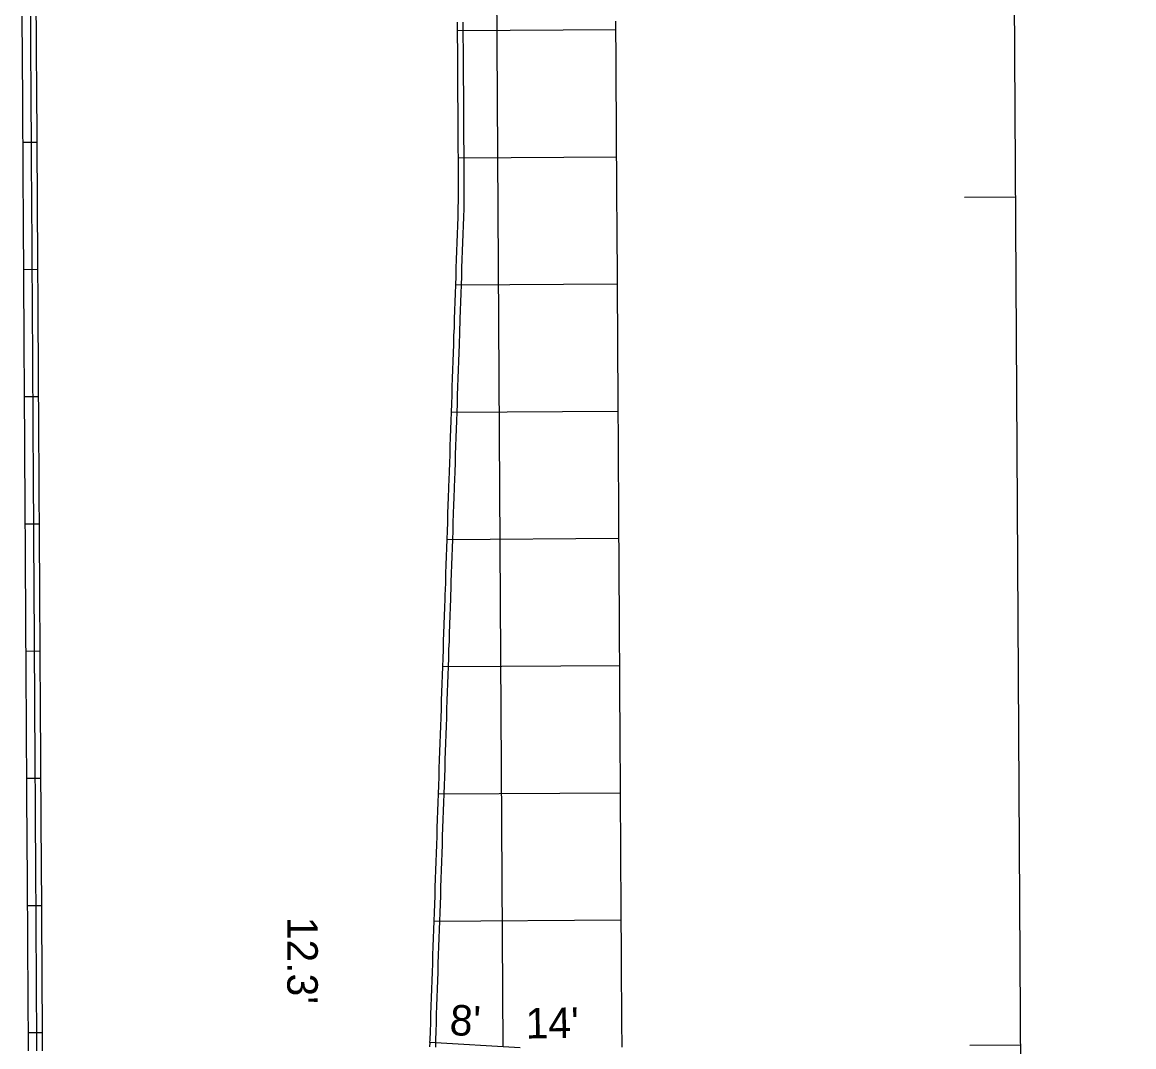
# Model space of a CAD drawing. Extents: x 2145147 to 2158018, y 137519 to 148068.
# Drawn here: x 2150693.6 to 2150824.7, y 145218.9 to 145339.8 of the extents above; entities that cross this region are included whole.
import ezdxf

# ---------------------------------------------------------------- set-up
doc = ezdxf.new("R2010")
doc.units = 0
for name, color, linetype in [('EX_Align', 7, 'Continuous'), ('PR_Dimensions', 7, 'Continuous'), ('PR_Joint_Contraction', 7, 'Continuous'), ('PR_Joint_Isolation', 7, 'Continuous'), ('PR_Joint_Long', 7, 'Continuous'), ('PR_Road_Concrete', 7, 'Continuous')]:
    doc.layers.add(name, color=color, linetype=linetype)

msp = doc.modelspace()

# ---------------------------------------------------------------- linework, layer by layer
at = {"layer": 'EX_Align'}
msp.add_line((2150824.67, 142998.65), (2150804.61, 146336.84), dxfattribs=at)
for points in [[(2150804.72, 145319.13), (2150810.72, 145319.17)], [(2150805.32, 145219.13), (2150811.32, 145219.17)]]:
    msp.add_lwpolyline(points, dxfattribs=at)
at = {"layer": 'PR_Joint_Contraction'}
for p, q in [((2150744.94, 145338.78), (2150763.6, 145338.89)), ((2150693.69, 145325.61), (2150695.35, 145325.62)), ((2150745.03, 145323.78), (2150763.69, 145323.89)), ((2150693.78, 145310.61), (2150695.44, 145310.62)), ((2150744.72, 145308.78), (2150763.78, 145308.9)), ((2150693.87, 145295.61), (2150695.53, 145295.62)), ((2150744.21, 145293.78), (2150763.87, 145293.9)), ((2150693.96, 145280.61), (2150695.62, 145280.62)), ((2150743.7, 145278.77), (2150763.96, 145278.9)), ((2150694.05, 145265.61), (2150695.72, 145265.62)), ((2150743.19, 145263.77), (2150764.05, 145263.9)), ((2150694.14, 145250.61), (2150695.81, 145250.62)), ((2150742.68, 145248.77), (2150764.14, 145248.9)), ((2150694.23, 145235.61), (2150695.9, 145235.62)), ((2150742.17, 145233.76), (2150764.23, 145233.9)), ((2150694.32, 145220.61), (2150695.99, 145220.62))]:
    msp.add_line(p, q, dxfattribs=at)
at = {"layer": 'PR_Joint_Isolation'}
msp.add_line((2150752.32, 145218.82), (2150741.68, 145219.46), dxfattribs=at)
at = {"layer": 'PR_Joint_Long'}
for points in [[(2150750.32, 145218.94), (2150743.61, 146336.79)], [(2150764.32, 145218.9), (2150764.32, 145219.89), (2150764.31, 145220.89), (2150764.31, 145221.89), (2150764.3, 145222.89), (2150764.29, 145223.89), (2150764.29, 145224.89), (2150764.28, 145225.89), (2150764.28, 145226.89), (2150764.27, 145227.89), (2150764.26, 145228.89), (2150764.26, 145229.89), (2150764.25, 145230.89), (2150764.25, 145231.89), (2150764.24, 145232.89), (2150764.23, 145233.89), (2150764.23, 145234.89), (2150764.22, 145235.89), (2150764.22, 145236.89), (2150764.21, 145237.89), (2150764.2, 145238.89), (2150764.2, 145239.89), (2150764.19, 145240.89), (2150764.19, 145241.89), (2150764.18, 145242.89), (2150764.17, 145243.89), (2150764.17, 145244.89), (2150764.16, 145245.89), (2150764.16, 145246.89), (2150764.15, 145247.89), (2150764.14, 145248.89), (2150764.14, 145249.89), (2150764.13, 145250.89), (2150764.13, 145251.89), (2150764.12, 145252.89), (2150764.11, 145253.89), (2150764.11, 145254.89), (2150764.1, 145255.89), (2150764.1, 145256.89), (2150764.09, 145257.89), (2150764.08, 145258.89), (2150764.08, 145259.89), (2150764.07, 145260.89), (2150764.07, 145261.89), (2150764.06, 145262.89), (2150764.05, 145263.89), (2150764.05, 145264.89), (2150764.04, 145265.89), (2150764.04, 145266.89), (2150764.03, 145267.89), (2150764.02, 145268.78), (2150764.02, 145268.89), (2150764.02, 145269.89), (2150764.01, 145270.89), (2150764.01, 145271.89), (2150764, 145272.49), (2150764, 145272.89), (2150763.99, 145273.89), (2150763.99, 145274.89), (2150763.98, 145275.89), (2150763.98, 145276.89), (2150763.97, 145277.89), (2150763.96, 145278.89), (2150763.96, 145279.89), (2150763.95, 145280.89), (2150763.95, 145281.89), (2150763.94, 145282), (2150763.94, 145282.89), (2150763.93, 145283.89), (2150763.93, 145284.89), (2150763.93, 145285.18), (2150763.92, 145285.89), (2150763.92, 145286.89), (2150763.91, 145287.89), (2150763.9, 145288.89), (2150763.9, 145289.89), (2150763.89, 145290.89), (2150763.89, 145291.89), (2150763.88, 145292.89), (2150763.87, 145293.89), (2150763.87, 145294.89), (2150763.86, 145295.89), (2150763.86, 145296.89), (2150763.85, 145297.89), (2150763.84, 145298.89), (2150763.84, 145299.89), (2150763.83, 145300.89), (2150763.83, 145301.89), (2150763.82, 145302.27), (2150763.82, 145302.89), (2150763.81, 145303.89), (2150763.81, 145304.18), (2150763.81, 145304.89), (2150763.8, 145305.89), (2150763.8, 145306.89), (2150763.79, 145307.89), (2150763.78, 145308.89), (2150763.78, 145309.89), (2150763.77, 145310.89), (2150763.77, 145311.89), (2150763.76, 145312.89), (2150763.75, 145313.89), (2150763.75, 145314.89), (2150763.74, 145315.89), (2150763.74, 145316.89), (2150763.73, 145317.89), (2150763.72, 145318.89), (2150763.72, 145319.89), (2150763.71, 145320.89), (2150763.71, 145321.89), (2150763.7, 145322.89), (2150763.69, 145323.89), (2150763.69, 145324.89), (2150763.68, 145325.89), (2150763.68, 145326.89), (2150763.67, 145327.89), (2150763.66, 145328.89), (2150763.66, 145329.89), (2150763.65, 145330.89), (2150763.65, 145331.89), (2150763.64, 145332.89), (2150763.63, 145333.89), (2150763.63, 145334.89), (2150763.62, 145335.89), (2150763.62, 145336.89), (2150763.61, 145337.89), (2150763.6, 145338.89), (2150763.6, 145339.89)]]:
    msp.add_lwpolyline(points, dxfattribs=at)
at = {"layer": 'PR_Road_Concrete'}
for points in [[(2150694.33, 145218.47), (2150694.33, 145219.47), (2150694.32, 145220.47), (2150694.32, 145221.47), (2150694.31, 145222.47), (2150694.3, 145223.47), (2150694.3, 145224.47), (2150694.29, 145225.47), (2150694.29, 145226.47), (2150694.28, 145227.47), (2150694.27, 145228.47), (2150694.27, 145229.47), (2150694.26, 145230.47), (2150694.26, 145231.47), (2150694.25, 145232.47), (2150694.24, 145233.47), (2150694.24, 145234.47), (2150694.23, 145235.47), (2150694.23, 145236.47), (2150694.22, 145237.47), (2150694.21, 145238.47), (2150694.21, 145239.47), (2150694.2, 145240.47), (2150694.19, 145241.47), (2150694.19, 145242.47), (2150694.18, 145243.47), (2150694.18, 145244.47), (2150694.17, 145245.47), (2150694.16, 145246.47), (2150694.16, 145247.47), (2150694.15, 145248.47), (2150694.15, 145249.47), (2150694.14, 145250.47), (2150694.13, 145251.47), (2150694.13, 145252.47), (2150694.12, 145253.47), (2150694.12, 145254.47), (2150694.11, 145255.47), (2150694.1, 145256.47), (2150694.1, 145257.47), (2150694.09, 145258.47), (2150694.09, 145259.47), (2150694.08, 145260.47), (2150694.07, 145261.47), (2150694.07, 145262.47), (2150694.06, 145263.47), (2150694.06, 145264.47), (2150694.05, 145265.47), (2150694.04, 145266.47), (2150694.04, 145267.47), (2150694.03, 145268.47), (2150694.03, 145269.47), (2150694.02, 145270.47), (2150694.01, 145271.47), (2150694.01, 145272.47), (2150694, 145273.47), (2150694, 145274.47), (2150693.99, 145275.47), (2150693.98, 145276.47), (2150693.98, 145277.47), (2150693.97, 145278.47), (2150693.97, 145279.47), (2150693.96, 145280.47), (2150693.95, 145281.47), (2150693.95, 145282.47), (2150693.94, 145283.47), (2150693.93, 145284.47), (2150693.93, 145285.47), (2150693.92, 145286.47), (2150693.92, 145287.47), (2150693.91, 145288.47), (2150693.9, 145289.47), (2150693.9, 145290.47), (2150693.89, 145291.47), (2150693.89, 145292.47), (2150693.88, 145293.47), (2150693.87, 145294.47), (2150693.87, 145295.47), (2150693.86, 145296.47), (2150693.86, 145297.47), (2150693.85, 145298.47), (2150693.84, 145299.47), (2150693.84, 145300.47), (2150693.83, 145301.47), (2150693.83, 145302.47), (2150693.82, 145303.47), (2150693.81, 145304.47), (2150693.81, 145305.47), (2150693.8, 145306.47), (2150693.8, 145307.47), (2150693.79, 145308.47), (2150693.78, 145309.47), (2150693.78, 145310.47), (2150693.77, 145311.47), (2150693.77, 145312.47), (2150693.76, 145313.47), (2150693.75, 145314.47), (2150693.75, 145315.47), (2150693.74, 145316.47), (2150693.74, 145317.47), (2150693.73, 145318.47), (2150693.72, 145319.47), (2150693.72, 145320.47), (2150693.71, 145321.47), (2150693.71, 145322.47), (2150693.7, 145323.47), (2150693.69, 145324.47), (2150693.69, 145325.47), (2150693.68, 145326.47), (2150693.68, 145327.47), (2150693.67, 145328.47), (2150693.66, 145329.47), (2150693.66, 145330.47), (2150693.65, 145331.47), (2150693.65, 145332.47), (2150693.64, 145333.47), (2150693.63, 145334.47), (2150693.63, 145335.47), (2150693.62, 145336.47), (2150693.62, 145337.47), (2150693.61, 145338.47), (2150693.6, 145339.47), (2150693.6, 145340.47)], [(2150695.33, 145218.48), (2150695.33, 145219.48), (2150695.32, 145220.48), (2150695.32, 145221.48), (2150695.31, 145222.48), (2150695.3, 145223.48), (2150695.3, 145224.48), (2150695.29, 145225.48), (2150695.29, 145226.48), (2150695.28, 145227.48), (2150695.27, 145228.48), (2150695.27, 145229.48), (2150695.26, 145230.48), (2150695.26, 145231.48), (2150695.25, 145232.48), (2150695.24, 145233.48), (2150695.24, 145234.48), (2150695.23, 145235.48), (2150695.23, 145236.48), (2150695.22, 145237.48), (2150695.21, 145238.48), (2150695.21, 145239.48), (2150695.2, 145240.48), (2150695.19, 145241.48), (2150695.19, 145242.48), (2150695.18, 145243.48), (2150695.18, 145244.48), (2150695.17, 145245.48), (2150695.16, 145246.48), (2150695.16, 145247.48), (2150695.15, 145248.48), (2150695.15, 145249.48), (2150695.14, 145250.48), (2150695.13, 145251.48), (2150695.13, 145252.48), (2150695.12, 145253.48), (2150695.12, 145254.48), (2150695.11, 145255.48), (2150695.1, 145256.48), (2150695.1, 145257.48), (2150695.09, 145258.48), (2150695.09, 145259.48), (2150695.08, 145260.48), (2150695.07, 145261.48), (2150695.07, 145262.48), (2150695.06, 145263.48), (2150695.06, 145264.48), (2150695.05, 145265.48), (2150695.04, 145266.48), (2150695.04, 145267.48), (2150695.03, 145268.48), (2150695.03, 145269.48), (2150695.02, 145270.48), (2150695.01, 145271.48), (2150695.01, 145272.48), (2150695, 145273.48), (2150695, 145274.48), (2150694.99, 145275.48), (2150694.98, 145276.48), (2150694.98, 145277.48), (2150694.97, 145278.48), (2150694.97, 145279.48), (2150694.96, 145280.48), (2150694.95, 145281.48), (2150694.95, 145282.48), (2150694.94, 145283.48), (2150694.93, 145284.48), (2150694.93, 145285.48), (2150694.92, 145286.48), (2150694.92, 145287.48), (2150694.91, 145288.48), (2150694.9, 145289.48), (2150694.9, 145290.48), (2150694.89, 145291.48), (2150694.89, 145292.48), (2150694.88, 145293.48), (2150694.87, 145294.48), (2150694.87, 145295.48), (2150694.86, 145296.48), (2150694.86, 145297.48), (2150694.85, 145298.48), (2150694.84, 145299.48), (2150694.84, 145300.48), (2150694.83, 145301.48), (2150694.83, 145302.48), (2150694.82, 145303.48), (2150694.81, 145304.48), (2150694.81, 145305.48), (2150694.8, 145306.48), (2150694.8, 145307.48), (2150694.79, 145308.48), (2150694.78, 145309.48), (2150694.78, 145310.48), (2150694.77, 145311.48), (2150694.77, 145312.48), (2150694.76, 145313.48), (2150694.75, 145314.48), (2150694.75, 145315.48), (2150694.74, 145316.48), (2150694.74, 145317.48), (2150694.73, 145318.48), (2150694.72, 145319.48), (2150694.72, 145320.48), (2150694.71, 145321.48), (2150694.71, 145322.48), (2150694.7, 145323.48), (2150694.69, 145324.48), (2150694.69, 145325.48), (2150694.68, 145326.48), (2150694.68, 145327.48), (2150694.67, 145328.48), (2150694.66, 145329.48), (2150694.66, 145330.48), (2150694.65, 145331.48), (2150694.65, 145332.48), (2150694.64, 145333.48), (2150694.63, 145334.48), (2150694.63, 145335.48), (2150694.62, 145336.48), (2150694.62, 145337.48), (2150694.61, 145338.48), (2150694.6, 145339.48), (2150694.6, 145340.48)], [(2150696, 145218.48), (2150695.99, 145219.48), (2150695.99, 145220.48), (2150695.98, 145221.48), (2150695.98, 145222.48), (2150695.97, 145223.48), (2150695.96, 145224.48), (2150695.96, 145225.48), (2150695.95, 145226.48), (2150695.95, 145227.48), (2150695.94, 145228.48), (2150695.93, 145229.48), (2150695.93, 145230.48), (2150695.92, 145231.48), (2150695.92, 145232.48), (2150695.91, 145233.48), (2150695.9, 145234.48), (2150695.9, 145235.48), (2150695.89, 145236.48), (2150695.89, 145237.48), (2150695.88, 145238.48), (2150695.87, 145239.48), (2150695.87, 145240.48), (2150695.86, 145241.48), (2150695.86, 145242.48), (2150695.85, 145243.48), (2150695.84, 145244.48), (2150695.84, 145245.48), (2150695.83, 145246.48), (2150695.83, 145247.48), (2150695.82, 145248.48), (2150695.81, 145249.48), (2150695.81, 145250.48), (2150695.8, 145251.48), (2150695.8, 145252.48), (2150695.79, 145253.48), (2150695.78, 145254.48), (2150695.78, 145255.48), (2150695.77, 145256.48), (2150695.76, 145257.48), (2150695.76, 145258.48), (2150695.75, 145259.48), (2150695.75, 145260.48), (2150695.74, 145261.48), (2150695.73, 145262.48), (2150695.73, 145263.48), (2150695.72, 145264.48), (2150695.72, 145265.48), (2150695.71, 145266.48), (2150695.7, 145267.48), (2150695.7, 145268.48), (2150695.69, 145269.48), (2150695.69, 145270.48), (2150695.68, 145271.48), (2150695.67, 145272.48), (2150695.67, 145273.48), (2150695.66, 145274.48), (2150695.66, 145275.48), (2150695.65, 145276.48), (2150695.64, 145277.48), (2150695.64, 145278.48), (2150695.63, 145279.48), (2150695.63, 145280.48), (2150695.62, 145281.48), (2150695.61, 145282.48), (2150695.61, 145283.48), (2150695.6, 145284.48), (2150695.6, 145285.48), (2150695.59, 145286.48), (2150695.58, 145287.48), (2150695.58, 145288.48), (2150695.57, 145289.48), (2150695.57, 145290.48), (2150695.56, 145291.48), (2150695.55, 145292.48), (2150695.55, 145293.48), (2150695.54, 145294.48), (2150695.53, 145295.48), (2150695.53, 145296.48), (2150695.52, 145297.48), (2150695.52, 145298.48), (2150695.51, 145299.48), (2150695.5, 145300.48), (2150695.5, 145301.48), (2150695.49, 145302.48), (2150695.49, 145303.48), (2150695.48, 145304.48), (2150695.47, 145305.48), (2150695.47, 145306.48), (2150695.46, 145307.48), (2150695.46, 145308.48), (2150695.45, 145309.48), (2150695.44, 145310.48), (2150695.44, 145311.48), (2150695.43, 145312.48), (2150695.43, 145313.48), (2150695.42, 145314.48), (2150695.41, 145315.48), (2150695.41, 145316.48), (2150695.4, 145317.48), (2150695.4, 145318.48), (2150695.39, 145319.48), (2150695.38, 145320.48), (2150695.38, 145321.48), (2150695.37, 145322.48), (2150695.37, 145323.48), (2150695.36, 145324.48), (2150695.35, 145325.48), (2150695.35, 145326.48), (2150695.34, 145327.48), (2150695.34, 145328.48), (2150695.33, 145329.48), (2150695.32, 145330.48), (2150695.32, 145331.48), (2150695.31, 145332.48), (2150695.31, 145333.48), (2150695.3, 145334.48), (2150695.29, 145335.48), (2150695.29, 145336.48), (2150695.28, 145337.48), (2150695.28, 145338.48), (2150695.27, 145339.48), (2150695.26, 145340.48)], [(2150741.68, 145219.46), (2150741.69, 145219.75), (2150741.73, 145220.75), (2150741.76, 145221.75), (2150741.79, 145222.75), (2150741.83, 145223.75), (2150741.86, 145224.75), (2150741.9, 145225.75), (2150741.93, 145226.75), (2150741.96, 145227.75), (2150742, 145228.75), (2150742.03, 145229.75), (2150742.07, 145230.76), (2150742.1, 145231.76), (2150742.13, 145232.76), (2150742.17, 145233.76), (2150742.2, 145234.76), (2150742.24, 145235.76), (2150742.27, 145236.76), (2150742.3, 145237.76), (2150742.34, 145238.76), (2150742.37, 145239.76), (2150742.41, 145240.76), (2150742.44, 145241.76), (2150742.47, 145242.76), (2150742.51, 145243.76), (2150742.54, 145244.76), (2150742.58, 145245.76), (2150742.61, 145246.76), (2150742.64, 145247.76), (2150742.68, 145248.76), (2150742.71, 145249.76), (2150742.75, 145250.76), (2150742.78, 145251.76), (2150742.81, 145252.76), (2150742.85, 145253.76), (2150742.88, 145254.76), (2150742.92, 145255.76), (2150742.95, 145256.76), (2150742.98, 145257.76), (2150743.02, 145258.76), (2150743.05, 145259.76), (2150743.09, 145260.76), (2150743.12, 145261.76), (2150743.15, 145262.76), (2150743.19, 145263.76), (2150743.22, 145264.76), (2150743.26, 145265.76), (2150743.29, 145266.76), (2150743.32, 145267.76), (2150743.35, 145268.65), (2150743.36, 145268.76), (2150743.39, 145269.76), (2150743.43, 145270.76), (2150743.46, 145271.76), (2150743.48, 145272.36), (2150743.49, 145272.76), (2150743.53, 145273.76), (2150743.56, 145274.76), (2150743.6, 145275.77), (2150743.63, 145276.77), (2150743.66, 145277.77), (2150743.7, 145278.77), (2150743.73, 145279.77), (2150743.77, 145280.77), (2150743.8, 145281.77), (2150743.8, 145281.88), (2150743.83, 145282.77), (2150743.87, 145283.77), (2150743.9, 145284.77), (2150743.91, 145285.06), (2150743.94, 145285.77), (2150743.97, 145286.77), (2150744, 145287.77), (2150744.04, 145288.77), (2150744.07, 145289.77), (2150744.11, 145290.77), (2150744.14, 145291.77), (2150744.17, 145292.77), (2150744.21, 145293.77), (2150744.24, 145294.77), (2150744.28, 145295.77), (2150744.31, 145296.77), (2150744.34, 145297.77), (2150744.38, 145298.77), (2150744.41, 145299.77), (2150744.45, 145300.77), (2150744.48, 145301.77), (2150744.49, 145302.16), (2150744.51, 145302.77), (2150744.55, 145303.77), (2150744.56, 145304.07), (2150744.58, 145304.77), (2150744.62, 145305.77), (2150744.65, 145306.77), (2150744.68, 145307.77), (2150744.72, 145308.77), (2150744.75, 145309.77), (2150744.78, 145310.77), (2150744.82, 145311.77), (2150744.85, 145312.77), (2150744.89, 145313.77), (2150744.92, 145314.77), (2150744.95, 145315.77), (2150744.99, 145316.77), (2150745.02, 145317.77), (2150745.06, 145318.77), (2150745.05, 145319.77), (2150745.04, 145320.77), (2150745.04, 145321.77), (2150745.03, 145322.77), (2150745.03, 145323.77), (2150745.02, 145324.77), (2150745.01, 145325.77), (2150745.01, 145326.77), (2150745, 145327.77), (2150745, 145328.77), (2150744.99, 145329.77), (2150744.98, 145330.77), (2150744.98, 145331.77), (2150744.97, 145332.77), (2150744.97, 145333.77), (2150744.96, 145334.77), (2150744.95, 145335.77), (2150744.95, 145336.77), (2150744.94, 145337.77), (2150744.94, 145338.77), (2150744.93, 145339.77)], [(2150742.35, 145219.42), (2150742.36, 145219.76), (2150742.39, 145220.76), (2150742.43, 145221.76), (2150742.46, 145222.76), (2150742.49, 145223.76), (2150742.53, 145224.76), (2150742.56, 145225.76), (2150742.6, 145226.76), (2150742.63, 145227.76), (2150742.66, 145228.76), (2150742.7, 145229.76), (2150742.73, 145230.76), (2150742.77, 145231.76), (2150742.8, 145232.76), (2150742.83, 145233.76), (2150742.87, 145234.76), (2150742.9, 145235.76), (2150742.94, 145236.76), (2150742.97, 145237.76), (2150743, 145238.76), (2150743.04, 145239.76), (2150743.07, 145240.76), (2150743.11, 145241.76), (2150743.14, 145242.76), (2150743.17, 145243.76), (2150743.21, 145244.76), (2150743.24, 145245.76), (2150743.28, 145246.76), (2150743.31, 145247.76), (2150743.34, 145248.76), (2150743.38, 145249.76), (2150743.41, 145250.76), (2150743.45, 145251.76), (2150743.48, 145252.76), (2150743.51, 145253.76), (2150743.55, 145254.76), (2150743.58, 145255.76), (2150743.62, 145256.76), (2150743.65, 145257.77), (2150743.68, 145258.77), (2150743.72, 145259.77), (2150743.75, 145260.77), (2150743.79, 145261.77), (2150743.82, 145262.77), (2150743.85, 145263.77), (2150743.89, 145264.77), (2150743.92, 145265.77), (2150743.96, 145266.77), (2150743.99, 145267.77), (2150744.02, 145268.66), (2150744.02, 145268.77), (2150744.06, 145269.77), (2150744.09, 145270.77), (2150744.13, 145271.77), (2150744.15, 145272.37), (2150744.16, 145272.77), (2150744.19, 145273.77), (2150744.23, 145274.77), (2150744.26, 145275.77), (2150744.3, 145276.77), (2150744.33, 145277.77), (2150744.36, 145278.77), (2150744.4, 145279.77), (2150744.43, 145280.77), (2150744.47, 145281.77), (2150744.47, 145281.89), (2150744.5, 145282.77), (2150744.53, 145283.77), (2150744.57, 145284.77), (2150744.58, 145285.06), (2150744.6, 145285.77), (2150744.64, 145286.77), (2150744.67, 145287.77), (2150744.7, 145288.77), (2150744.74, 145289.77), (2150744.77, 145290.77), (2150744.81, 145291.77), (2150744.84, 145292.77), (2150744.87, 145293.77), (2150744.91, 145294.77), (2150744.94, 145295.77), (2150744.98, 145296.77), (2150745.01, 145297.77), (2150745.04, 145298.77), (2150745.08, 145299.77), (2150745.11, 145300.77), (2150745.15, 145301.77), (2150745.16, 145302.16), (2150745.18, 145302.78), (2150745.21, 145303.78), (2150745.22, 145304.07), (2150745.25, 145304.78), (2150745.28, 145305.78), (2150745.32, 145306.78), (2150745.35, 145307.78), (2150745.38, 145308.78), (2150745.42, 145309.78), (2150745.45, 145310.78), (2150745.49, 145311.78), (2150745.52, 145312.78), (2150745.55, 145313.78), (2150745.59, 145314.78), (2150745.62, 145315.78), (2150745.66, 145316.78), (2150745.69, 145317.78), (2150745.72, 145318.78), (2150745.72, 145319.78), (2150745.71, 145320.78), (2150745.71, 145321.78), (2150745.7, 145322.78), (2150745.69, 145323.78), (2150745.69, 145324.78), (2150745.68, 145325.78), (2150745.68, 145326.78), (2150745.67, 145327.78), (2150745.66, 145328.78), (2150745.66, 145329.78), (2150745.65, 145330.78), (2150745.65, 145331.78), (2150745.64, 145332.78), (2150745.63, 145333.78), (2150745.63, 145334.78), (2150745.62, 145335.78), (2150745.62, 145336.78), (2150745.61, 145337.78), (2150745.6, 145338.78), (2150745.6, 145339.78)], [(2150741.68, 145219.46), (2150741.64, 145218.92)], [(2150742.34, 145219.42), (2150742.31, 145218.88)]]:
    msp.add_lwpolyline(points, dxfattribs=at)

# ---------------------------------------------------------------- texts
at = {"layer": 'PR_Dimensions'}
for s, rotation, p in [("12.3'", 269.9996, (2150724.85, 145234.27)), ("8'", 356.1069, (2150743.92, 145220.36)), ("14'", 0.8193, (2150752.98, 145219.91))]:
    msp.add_text(s, height=3.6, rotation=rotation, dxfattribs=at).set_placement(p)

doc.saveas('drawing.dxf')
